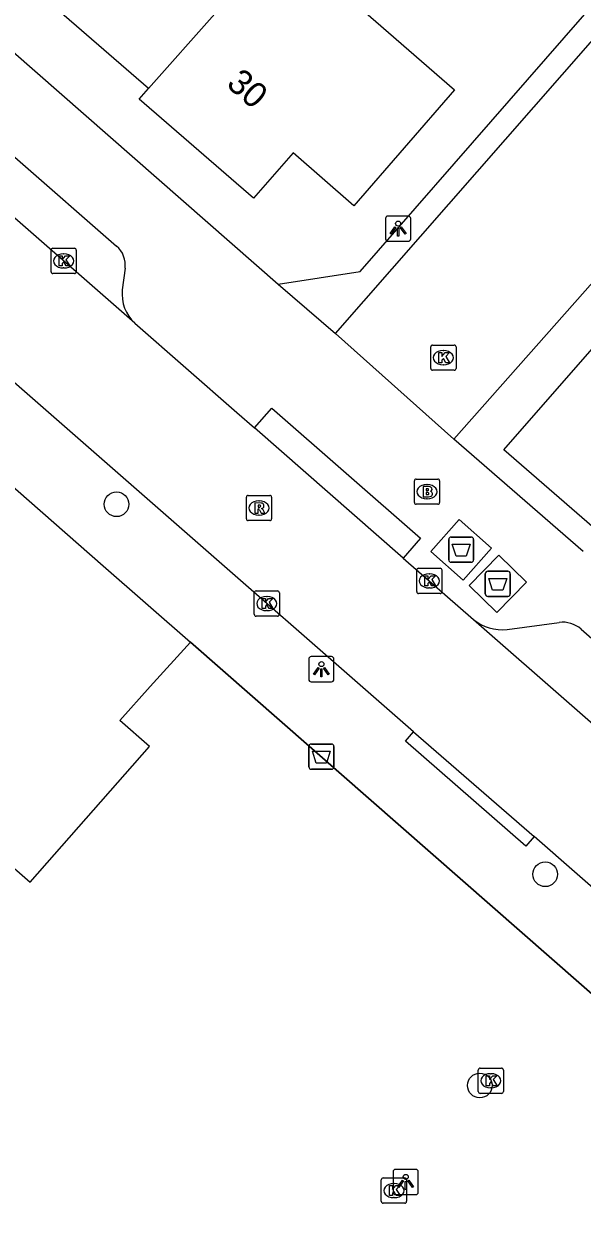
# Model space of a CAD drawing. Extents: x 158474 to 159560, y 388525 to 389605.
# Drawn here: x 158791.57 to 158813.69, y 388775.43 to 388822.77 of the extents above; entities that cross this region are included whole.
import ezdxf

# ---------------------------------------------------------------- set-up
doc = ezdxf.new("R2010")
doc.units = 0
for name, color, linetype in [('IMGEO_Afval_apart_plaats', 7, 'Continuous'), ('IMGEO_Afvalbak', 7, 'Continuous'), ('IMGEO_Boom', 7, 'Continuous'), ('IMGEO_Brandkraan', 7, 'Continuous'), ('IMGEO_Hek', 7, 'Continuous'), ('IMGEO_Kolk', 7, 'Continuous'), ('IMGEO_Lichtpunt', 7, 'Continuous'), ('IMGEO_Pand', 7, 'Continuous'), ('IMGEO_Pand_nummerreeks', 7, 'Continuous'), ('IMGEO_Rijbaan_lokaal_open', 7, 'Continuous'), ('IMGEO_Rioolput', 7, 'Continuous'), ('IMGEO_Voetpad_gesloten', 7, 'Continuous'), ('IMGEO_Voetpad_open', 7, 'Continuous')]:
    doc.layers.add(name, color=color, linetype=linetype)

msp = doc.modelspace()

# ---------------------------------------------------------------- linework, layer by layer
at = {"layer": 'IMGEO_Afval_apart_plaats'}
for p, q in [((158808.407, 388801.527), (158808.407, 388802.327)), ((158808.407, 388802.327), (158808.407, 388801.527)), ((158808.507, 388802.427), (158809.297, 388802.427)), ((158809.297, 388802.427), (158808.507, 388802.427)), ((158809.397, 388802.327), (158809.397, 388801.527)), ((158809.397, 388801.527), (158809.397, 388802.327)), ((158809.297, 388801.427), (158808.507, 388801.427)), ((158808.507, 388801.427), (158809.297, 388801.427)), ((158809.858, 388800.174), (158809.858, 388800.974)), ((158809.858, 388800.974), (158809.858, 388800.174)), ((158809.958, 388801.074), (158810.748, 388801.074)), ((158810.748, 388801.074), (158809.958, 388801.074)), ((158810.848, 388800.974), (158810.848, 388800.174)), ((158810.848, 388800.174), (158810.848, 388800.974)), ((158810.748, 388800.074), (158809.958, 388800.074)), ((158809.958, 388800.074), (158810.748, 388800.074))]:
    msp.add_line(p, q, dxfattribs=at)
for points in [[(158808.55, 388802.141), (158809.254, 388802.141), (158809.105, 388801.671), (158808.699, 388801.671), (158808.55, 388802.141)], [(158810.001, 388800.788), (158810.705, 388800.788), (158810.556, 388800.318), (158810.15, 388800.318), (158810.001, 388800.788)]]:
    msp.add_lwpolyline(points, dxfattribs=at)
for centre, start, end in [((158808.507, 388802.327), 90, 180), ((158808.507, 388802.327), 90, 180), ((158809.297, 388802.327), 0, 90), ((158809.297, 388802.327), 360, 90), ((158808.507, 388801.527), 180, 270), ((158808.507, 388801.527), 180, 270), ((158809.297, 388801.527), 270, 0), ((158809.297, 388801.527), 270, 0), ((158809.958, 388800.974), 90, 180), ((158809.958, 388800.974), 90, 180), ((158810.748, 388800.974), 0, 90), ((158810.748, 388800.974), 360, 90), ((158809.958, 388800.174), 180, 270), ((158809.958, 388800.174), 180, 270), ((158810.748, 388800.174), 270, 0), ((158810.748, 388800.174), 270, 0)]:
    msp.add_arc(centre, 0.1, start, end, dxfattribs=at)
at = {"layer": 'IMGEO_Afvalbak'}
for p, q in [((158802.968, 388794.224), (158803.758, 388794.224)), ((158803.758, 388794.224), (158802.968, 388794.224)), ((158802.868, 388793.324), (158802.868, 388794.124)), ((158802.868, 388794.124), (158802.868, 388793.324)), ((158803.858, 388794.124), (158803.858, 388793.324)), ((158803.858, 388793.324), (158803.858, 388794.124)), ((158803.758, 388793.224), (158802.968, 388793.224)), ((158802.968, 388793.224), (158803.758, 388793.224))]:
    msp.add_line(p, q, dxfattribs=at)
msp.add_lwpolyline([(158803.011, 388793.938), (158803.715, 388793.938), (158803.566, 388793.468), (158803.16, 388793.468), (158803.011, 388793.938)], dxfattribs=at)
for centre, start, end in [((158802.968, 388794.124), 90, 180), ((158802.968, 388794.124), 90, 180), ((158803.758, 388794.124), 0, 90), ((158803.758, 388794.124), 360, 90), ((158802.968, 388793.324), 180, 270), ((158802.968, 388793.324), 180, 270), ((158803.758, 388793.324), 270, 0), ((158803.758, 388793.324), 270, 0)]:
    msp.add_arc(centre, 0.1, start, end, dxfattribs=at)
at = {"layer": 'IMGEO_Boom'}
for centre in [(158795.246, 388803.729), (158812.232, 388789.064), (158809.641, 388780.692)]:
    msp.add_circle(centre, 0.489, dxfattribs=at)
at = {"layer": 'IMGEO_Brandkraan'}
for p, q in [((158807.048, 388803.801), (158807.048, 388804.653)), ((158807.123, 388804.727), (158807.975, 388804.727)), ((158808.049, 388804.653), (158808.049, 388803.801)), ((158807.536, 388804.507), (158807.561, 388804.507)), ((158807.975, 388803.727), (158807.123, 388803.727)), ((158807.559, 388803.947), (158807.534, 388803.947))]:
    msp.add_line(p, q, dxfattribs=at)
for points in [[(158807.048, 388803.801), (158807.048, 388804.653)], [(158807.123, 388804.727), (158807.975, 388804.727)], [(158808.049, 388804.653), (158808.049, 388803.801)], [(158807.396, 388804.427), (158807.396, 388804.027), (158807.609, 388804.027)], [(158807.627, 388804.427), (158807.396, 388804.427)], [(158807.575, 388804.346), (158807.521, 388804.346), (158807.521, 388804.27)], [(158807.521, 388804.27), (158807.574, 388804.27)], [(158807.583, 388804.194), (158807.521, 388804.194), (158807.521, 388804.113)], [(158807.521, 388804.113), (158807.583, 388804.113)], [(158807.975, 388803.727), (158807.123, 388803.727)]]:
    msp.add_lwpolyline(points, dxfattribs=at)
for centre, radius, start, end in [((158807.125, 388804.651), 0.0765, 91.552, 178.448), ((158807.125, 388804.651), 0.0765, 91.552, 178.448), ((158807.973, 388804.651), 0.0765, 1.552, 88.448), ((158807.973, 388804.651), 0.0765, 1.552, 88.448), ((158807.576, 388804.308), 0.0379, 267.8285, 90.9355), ((158807.584, 388804.153), 0.0404, 269.8759, 90.5077), ((158807.631, 388804.282), 0.145, 59.4692, 91.5367), ((158807.656, 388804.329), 0.0922, 285.5137, 58.1501), ((158807.661, 388804.137), 0.105, 301.3115, 78.989), ((158807.125, 388803.803), 0.0765, 181.552, 268.448), ((158807.125, 388803.803), 0.0765, 181.552, 268.448), ((158807.615, 388804.278), 0.251, 268.6676, 293.5347), ((158807.973, 388803.803), 0.0765, 271.552, 358.448), ((158807.973, 388803.803), 0.0765, 271.552, 358.448)]:
    msp.add_arc(centre, radius, start, end, dxfattribs=at)
for centre, major_axis, ratio, start_param, end_param in [((158807.535, 388804.227), (-0.387, 0.002), 0.722429, 4.712389, 7.853982), ((158807.56, 388804.227), (-0.39, 0.002), 0.717154, 1.570796, 4.712389)]:
    msp.add_ellipse(centre, major_axis=major_axis, ratio=ratio, start_param=start_param, end_param=end_param, dxfattribs=at)
at = {"layer": 'IMGEO_Hek'}
msp.add_lwpolyline([(158825.526, 388774.279), (158798.172, 388798.264)], dxfattribs=at)
at = {"layer": 'IMGEO_Kolk'}
for p, q in [((158792.65, 388812.947), (158792.65, 388813.799)), ((158792.725, 388813.873), (158793.577, 388813.873)), ((158793.138, 388813.653), (158793.163, 388813.653)), ((158793.651, 388813.799), (158793.651, 388812.947)), ((158793.161, 388813.093), (158793.136, 388813.093)), ((158793.577, 388812.873), (158792.725, 388812.873)), ((158807.697, 388809.113), (158807.697, 388809.965)), ((158807.772, 388810.039), (158808.624, 388810.039)), ((158808.185, 388809.819), (158808.21, 388809.819)), ((158808.698, 388809.965), (158808.698, 388809.113)), ((158808.624, 388809.039), (158807.772, 388809.039)), ((158808.208, 388809.259), (158808.183, 388809.259)), ((158807.141, 388800.265), (158807.141, 388801.117)), ((158807.216, 388801.191), (158808.068, 388801.191)), ((158807.629, 388800.971), (158807.654, 388800.971)), ((158808.142, 388801.117), (158808.142, 388800.265)), ((158800.774, 388800.293), (158801.626, 388800.293)), ((158807.652, 388800.411), (158807.627, 388800.411)), ((158800.699, 388799.367), (158800.699, 388800.219)), ((158801.187, 388800.073), (158801.212, 388800.073)), ((158801.7, 388800.219), (158801.7, 388799.367)), ((158808.068, 388800.191), (158807.216, 388800.191)), ((158801.21, 388799.513), (158801.185, 388799.513)), ((158801.626, 388799.293), (158800.774, 388799.293)), ((158809.652, 388781.379), (158810.504, 388781.379)), ((158809.577, 388780.453), (158809.577, 388781.305)), ((158810.065, 388781.159), (158810.09, 388781.159)), ((158810.578, 388781.305), (158810.578, 388780.453)), ((158810.088, 388780.599), (158810.063, 388780.599)), ((158810.504, 388780.379), (158809.652, 388780.379)), ((158805.737, 388776.1), (158805.737, 388776.952)), ((158805.812, 388777.026), (158806.664, 388777.026)), ((158806.225, 388776.806), (158806.25, 388776.806)), ((158806.738, 388776.952), (158806.738, 388776.1)), ((158806.248, 388776.246), (158806.223, 388776.246)), ((158806.664, 388776.026), (158805.812, 388776.026))]:
    msp.add_line(p, q, dxfattribs=at)
for points in [[(158792.65, 388812.947), (158792.65, 388813.799)], [(158792.725, 388813.873), (158793.577, 388813.873)], [(158792.971, 388813.573), (158793.094, 388813.573), (158793.094, 388813.422), (158793.224, 388813.573), (158793.388, 388813.573), (158793.242, 388813.422), (158793.395, 388813.173), (158793.243, 388813.173), (158793.158, 388813.337), (158793.094, 388813.27), (158793.094, 388813.173), (158792.971, 388813.173), (158792.971, 388813.573)], [(158793.651, 388813.799), (158793.651, 388812.947)], [(158793.577, 388812.873), (158792.725, 388812.873)], [(158807.697, 388809.113), (158807.697, 388809.965)], [(158807.772, 388810.039), (158808.624, 388810.039)], [(158808.698, 388809.965), (158808.698, 388809.113)], [(158808.018, 388809.739), (158808.141, 388809.739), (158808.141, 388809.588), (158808.271, 388809.739), (158808.435, 388809.739), (158808.289, 388809.588), (158808.442, 388809.339), (158808.29, 388809.339), (158808.205, 388809.503), (158808.141, 388809.436), (158808.141, 388809.339), (158808.018, 388809.339), (158808.018, 388809.739)], [(158808.624, 388809.039), (158807.772, 388809.039)], [(158807.141, 388800.265), (158807.141, 388801.117)], [(158807.216, 388801.191), (158808.068, 388801.191)], [(158807.462, 388800.891), (158807.585, 388800.891), (158807.585, 388800.74), (158807.715, 388800.891), (158807.879, 388800.891), (158807.733, 388800.74), (158807.886, 388800.491), (158807.734, 388800.491), (158807.649, 388800.655), (158807.585, 388800.588), (158807.585, 388800.491), (158807.462, 388800.491), (158807.462, 388800.891)], [(158808.142, 388801.117), (158808.142, 388800.265)], [(158800.774, 388800.293), (158801.626, 388800.293)], [(158800.699, 388799.367), (158800.699, 388800.219)], [(158801.02, 388799.993), (158801.143, 388799.993), (158801.143, 388799.842), (158801.273, 388799.993), (158801.437, 388799.993), (158801.291, 388799.842), (158801.444, 388799.593), (158801.292, 388799.593), (158801.207, 388799.757), (158801.143, 388799.69), (158801.143, 388799.593), (158801.02, 388799.593), (158801.02, 388799.993)], [(158801.7, 388800.219), (158801.7, 388799.367)], [(158808.068, 388800.191), (158807.216, 388800.191)], [(158801.626, 388799.293), (158800.774, 388799.293)], [(158809.652, 388781.379), (158810.504, 388781.379)], [(158809.577, 388780.453), (158809.577, 388781.305)], [(158809.898, 388781.079), (158810.021, 388781.079), (158810.021, 388780.928), (158810.151, 388781.079), (158810.315, 388781.079), (158810.169, 388780.928), (158810.322, 388780.679), (158810.17, 388780.679), (158810.085, 388780.843), (158810.021, 388780.776), (158810.021, 388780.679), (158809.898, 388780.679), (158809.898, 388781.079)], [(158810.578, 388781.305), (158810.578, 388780.453)], [(158810.504, 388780.379), (158809.652, 388780.379)], [(158805.737, 388776.1), (158805.737, 388776.952)], [(158805.812, 388777.026), (158806.664, 388777.026)], [(158806.058, 388776.726), (158806.181, 388776.726), (158806.181, 388776.575), (158806.311, 388776.726), (158806.475, 388776.726), (158806.329, 388776.575), (158806.482, 388776.326), (158806.33, 388776.326), (158806.245, 388776.49), (158806.181, 388776.423), (158806.181, 388776.326), (158806.058, 388776.326), (158806.058, 388776.726)], [(158806.738, 388776.952), (158806.738, 388776.1)], [(158806.664, 388776.026), (158805.812, 388776.026)]]:
    msp.add_lwpolyline(points, dxfattribs=at)
for centre, start, end in [((158792.727, 388813.797), 91.552, 178.448), ((158792.727, 388813.797), 91.552, 178.448), ((158793.575, 388813.797), 1.552, 88.448), ((158793.575, 388813.797), 1.552, 88.448), ((158792.727, 388812.949), 181.552, 268.448), ((158792.727, 388812.949), 181.552, 268.448), ((158793.575, 388812.949), 271.552, 358.448), ((158793.575, 388812.949), 271.552, 358.448), ((158807.774, 388809.963), 91.552, 178.448), ((158807.774, 388809.963), 91.552, 178.448), ((158808.622, 388809.963), 1.552, 88.448), ((158808.622, 388809.963), 1.552, 88.448), ((158807.774, 388809.115), 181.552, 268.448), ((158807.774, 388809.115), 181.552, 268.448), ((158808.622, 388809.115), 271.552, 358.448), ((158808.622, 388809.115), 271.552, 358.448), ((158807.218, 388801.115), 91.552, 178.448), ((158807.218, 388801.115), 91.552, 178.448), ((158808.066, 388801.115), 1.552, 88.448), ((158808.066, 388801.115), 1.552, 88.448), ((158800.776, 388800.217), 91.552, 178.448), ((158800.776, 388800.217), 91.552, 178.448), ((158801.624, 388800.217), 1.552, 88.448), ((158801.624, 388800.217), 1.552, 88.448), ((158807.218, 388800.267), 181.552, 268.448), ((158807.218, 388800.267), 181.552, 268.448), ((158808.066, 388800.267), 271.552, 358.448), ((158808.066, 388800.267), 271.552, 358.448), ((158800.776, 388799.369), 181.552, 268.448), ((158800.776, 388799.369), 181.552, 268.448), ((158801.624, 388799.369), 271.552, 358.448), ((158801.624, 388799.369), 271.552, 358.448), ((158809.654, 388781.303), 91.552, 178.448), ((158809.654, 388781.303), 91.552, 178.448), ((158810.502, 388781.303), 1.552, 88.448), ((158810.502, 388781.303), 1.552, 88.448), ((158809.654, 388780.455), 181.552, 268.448), ((158809.654, 388780.455), 181.552, 268.448), ((158810.502, 388780.455), 271.552, 358.448), ((158810.502, 388780.455), 271.552, 358.448), ((158805.814, 388776.95), 91.552, 178.448), ((158805.814, 388776.95), 91.552, 178.448), ((158806.662, 388776.95), 1.552, 88.448), ((158806.662, 388776.95), 1.552, 88.448), ((158805.814, 388776.102), 181.552, 268.448), ((158805.814, 388776.102), 181.552, 268.448), ((158806.662, 388776.102), 271.552, 358.448), ((158806.662, 388776.102), 271.552, 358.448)]:
    msp.add_arc(centre, 0.0765, start, end, dxfattribs=at)
for centre, major_axis, ratio, start_param, end_param in [((158793.137, 388813.373), (-0.387, 0.002), 0.722429, 4.712389, 7.853982), ((158793.162, 388813.373), (-0.39, 0.002), 0.717154, 1.570796, 4.712389), ((158808.184, 388809.539), (-0.387, 0.002), 0.722429, 4.712389, 7.853982), ((158808.209, 388809.539), (-0.39, 0.002), 0.717154, 1.570796, 4.712389), ((158807.628, 388800.691), (-0.387, 0.002), 0.722429, 4.712389, 7.853982), ((158807.653, 388800.691), (-0.39, 0.002), 0.717154, 1.570796, 4.712389), ((158801.186, 388799.793), (-0.387, 0.002), 0.722429, 4.712389, 7.853982), ((158801.211, 388799.793), (-0.39, 0.002), 0.717154, 1.570796, 4.712389), ((158810.064, 388780.879), (-0.387, 0.002), 0.722429, 4.712389, 7.853982), ((158810.089, 388780.879), (-0.39, 0.002), 0.717154, 1.570796, 4.712389), ((158806.224, 388776.526), (-0.387, 0.002), 0.722429, 4.712389, 7.853982), ((158806.249, 388776.526), (-0.39, 0.002), 0.717154, 1.570796, 4.712389)]:
    msp.add_ellipse(centre, major_axis=major_axis, ratio=ratio, start_param=start_param, end_param=end_param, dxfattribs=at)
at = {"layer": 'IMGEO_Lichtpunt'}
for p, q in [((158805.905, 388815.056), (158805.905, 388814.249)), ((158805.905, 388815.056), (158805.905, 388814.249)), ((158806.807, 388815.151), (158805.999, 388815.151)), ((158806.807, 388815.151), (158805.999, 388815.151)), ((158806.901, 388814.249), (158806.901, 388815.056)), ((158806.901, 388814.249), (158806.901, 388815.056)), ((158805.999, 388814.155), (158806.807, 388814.155)), ((158805.999, 388814.155), (158806.807, 388814.155)), ((158802.863, 388797.594), (158802.863, 388796.787)), ((158802.863, 388797.594), (158802.863, 388796.787)), ((158803.765, 388797.689), (158802.957, 388797.689)), ((158803.765, 388797.689), (158802.957, 388797.689)), ((158803.859, 388796.787), (158803.859, 388797.594)), ((158803.859, 388796.787), (158803.859, 388797.594)), ((158802.957, 388796.693), (158803.765, 388796.693)), ((158802.957, 388796.693), (158803.765, 388796.693)), ((158806.207, 388777.271), (158806.207, 388776.464)), ((158806.207, 388777.271), (158806.207, 388776.464)), ((158807.109, 388777.366), (158806.301, 388777.366)), ((158807.109, 388777.366), (158806.301, 388777.366)), ((158807.203, 388776.464), (158807.203, 388777.271)), ((158807.203, 388776.464), (158807.203, 388777.271)), ((158806.301, 388776.37), (158807.109, 388776.37)), ((158806.301, 388776.37), (158807.109, 388776.37))]:
    msp.add_line(p, q, dxfattribs=at)
for points in [[(158806.279, 388814.72), (158806.318, 388814.692), (158806.13, 388814.43), (158806.092, 388814.457), (158806.279, 388814.72)], [(158806.381, 388814.672), (158806.428, 388814.672), (158806.428, 388814.35), (158806.381, 388814.35), (158806.381, 388814.672)], [(158806.491, 388814.692), (158806.529, 388814.719), (158806.716, 388814.457), (158806.677, 388814.429), (158806.491, 388814.692)], [(158803.237, 388797.258), (158803.276, 388797.23), (158803.088, 388796.968), (158803.05, 388796.995), (158803.237, 388797.258)], [(158803.339, 388797.21), (158803.386, 388797.21), (158803.386, 388796.888), (158803.339, 388796.888), (158803.339, 388797.21)], [(158803.449, 388797.23), (158803.487, 388797.257), (158803.674, 388796.995), (158803.635, 388796.967), (158803.449, 388797.23)], [(158806.581, 388776.935), (158806.62, 388776.907), (158806.432, 388776.645), (158806.394, 388776.672), (158806.581, 388776.935)], [(158806.683, 388776.887), (158806.73, 388776.887), (158806.73, 388776.565), (158806.683, 388776.565), (158806.683, 388776.887)], [(158806.793, 388776.907), (158806.831, 388776.934), (158807.018, 388776.672), (158806.979, 388776.644), (158806.793, 388776.907)]]:
    msp.add_lwpolyline(points, dxfattribs=at)
for centre in [(158806.404, 388814.854), (158803.362, 388797.392), (158806.706, 388777.069)]:
    msp.add_circle(centre, 0.0994, dxfattribs=at)
for centre, start, end in [((158805.999, 388815.056), 90, 180), ((158805.999, 388815.056), 90, 180), ((158806.807, 388815.056), 0, 90), ((158806.807, 388815.056), 0, 90), ((158805.999, 388814.249), 180, 270), ((158805.999, 388814.249), 180, 270), ((158806.807, 388814.249), 270, 0), ((158806.807, 388814.249), 270, 360), ((158802.957, 388797.594), 90, 180), ((158802.957, 388797.594), 90, 180), ((158803.765, 388797.594), 0, 90), ((158803.765, 388797.594), 0, 90), ((158802.957, 388796.787), 180, 270), ((158802.957, 388796.787), 180, 270), ((158803.765, 388796.787), 270, 0), ((158803.765, 388796.787), 270, 360), ((158806.301, 388777.271), 90, 180), ((158806.301, 388777.271), 90, 180), ((158807.109, 388777.271), 0, 90), ((158807.109, 388777.271), 0, 90), ((158806.301, 388776.464), 180, 270), ((158806.301, 388776.464), 180, 270), ((158807.109, 388776.464), 270, 0), ((158807.109, 388776.464), 270, 360)]:
    msp.add_arc(centre, 0.0946, start, end, dxfattribs=at)
at = {"layer": 'IMGEO_Pand'}
for points in [[(158801.77, 388826.139), (158801.958, 388825.976), (158802.404, 388825.587), (158808.64, 388820.153), (158804.648, 388815.563), (158802.238, 388817.653), (158800.671, 388815.857), (158796.137, 388819.787), (158796.506, 388820.209)], [(158801.77, 388826.139), (158796.506, 388820.209)], [(158796.506, 388820.209), (158792.287, 388823.886)], [(158788.4, 388806.822), (158794.714, 388801.292), (158798.172, 388798.264)], [(158805.723, 388741.649), (158796.329, 388750), (158794.531, 388751.598), (158793.515, 388750.405), (158782.155, 388760.402), (158781.158, 388759.289), (158770.201, 388768.931), (158771.896, 388770.851), (158774.295, 388768.733), (158776.797, 388771.566), (158775.714, 388772.533), (158780.862, 388778.415), (158781.952, 388777.459), (158786.674, 388782.839), (158785.492, 388783.869), (158790.672, 388789.76), (158791.819, 388788.744), (158796.547, 388794.127), (158795.371, 388795.164), (158796.583, 388796.505), (158798.172, 388798.264)]]:
    msp.add_lwpolyline(points, dxfattribs=at)
at = {"layer": 'IMGEO_Rijbaan_lokaal_open'}
for points in [[(158795.971, 388810.903), (158760.339, 388842.098)], [(158803.922, 388810.501), (158817.392, 388825.895), (158820.104, 388828.995)], [(158824.946, 388824.766), (158822.181, 388821.641), (158808.612, 388806.31)], [(158807.018, 388794.713), (158796.782, 388803.661), (158782.389, 388816.244)], [(158795.971, 388810.903), (158800.014, 388807.365), (158800.712, 388806.754)], [(158808.612, 388806.31), (158803.922, 388810.501)], [(158806.606, 388801.596), (158800.712, 388806.754)], [(158806.606, 388801.596), (158809.387, 388799.161)], [(158809.387, 388799.161), (158825.712, 388784.875), (158827.828, 388783.04)], [(158807.018, 388794.713), (158811.795, 388790.555)], [(158826.434, 388774.844), (158827.866, 388776.475), (158811.795, 388790.555)]]:
    msp.add_lwpolyline(points, dxfattribs=at)
at = {"layer": 'IMGEO_Rioolput'}
for p, q in [((158800.466, 388804.08), (158801.318, 388804.08)), ((158800.391, 388803.154), (158800.391, 388804.006)), ((158800.879, 388803.86), (158800.904, 388803.86)), ((158801.392, 388804.006), (158801.392, 388803.154)), ((158800.902, 388803.3), (158800.877, 388803.3)), ((158801.318, 388803.08), (158800.466, 388803.08))]:
    msp.add_line(p, q, dxfattribs=at)
for points in [[(158800.466, 388804.08), (158801.318, 388804.08)], [(158800.391, 388803.154), (158800.391, 388804.006)], [(158800.98, 388803.778), (158800.728, 388803.78), (158800.728, 388803.38)], [(158800.906, 388803.699), (158800.852, 388803.699), (158800.852, 388803.618)], [(158800.852, 388803.618), (158800.904, 388803.618)], [(158801.392, 388804.006), (158801.392, 388803.154)], [(158800.728, 388803.38), (158800.852, 388803.38), (158800.852, 388803.542), (158800.863, 388803.542)], [(158800.91, 388803.513), (158800.981, 388803.38), (158801.121, 388803.38), (158801.056, 388803.506)], [(158801.318, 388803.08), (158800.466, 388803.08)]]:
    msp.add_lwpolyline(points, dxfattribs=at)
for centre, radius, start, end in [((158800.468, 388804.004), 0.0765, 91.552, 178.448), ((158800.468, 388804.004), 0.0765, 91.552, 178.448), ((158801.316, 388804.004), 0.0765, 1.552, 88.448), ((158801.316, 388804.004), 0.0765, 1.552, 88.448), ((158800.888, 388803.807), 0.19, 274.7715, 282.9687), ((158800.912, 388803.603), 0.0964, 77.0061, 93.1865), ((158800.926, 388803.66), 0.0378, 276.6634, 79.6772), ((158800.979, 388803.668), 0.109, 350.3612, 89.416), ((158800.977, 388803.668), 0.112, 277.5842, 350.9817), ((158800.468, 388803.156), 0.0765, 181.552, 268.448), ((158800.468, 388803.156), 0.0765, 181.552, 268.448), ((158800.862, 388803.489), 0.0533, 26.0293, 88.6989), ((158800.961, 388803.453), 0.108, 29.5134, 73.7905), ((158801.316, 388803.156), 0.0765, 271.552, 358.448), ((158801.316, 388803.156), 0.0765, 271.552, 358.448)]:
    msp.add_arc(centre, radius, start, end, dxfattribs=at)
for centre, major_axis, ratio, start_param, end_param in [((158800.878, 388803.58), (-0.387, 0.002), 0.722429, 4.712389, 7.853982), ((158800.903, 388803.58), (-0.39, 0.002), 0.717154, 1.570796, 4.712389)]:
    msp.add_ellipse(centre, major_axis=major_axis, ratio=ratio, start_param=start_param, end_param=end_param, dxfattribs=at)
at = {"layer": 'IMGEO_Voetpad_gesloten'}
for points in [[(158808.825, 388803.13), (158810.105, 388801.993), (158808.978, 388800.724), (158807.698, 388801.861), (158808.825, 388803.13)], [(158810.391, 388801.712), (158811.49, 388800.641), (158810.314, 388799.435), (158809.215, 388800.506), (158810.391, 388801.712)]]:
    msp.add_lwpolyline(points, dxfattribs=at)
at = {"layer": 'IMGEO_Voetpad_open'}
for points in [[(158801.652, 388812.449), (158804.894, 388812.957), (158816.712, 388826.499), (158846.015, 388860.076)], [(158763.278, 388846.106), (158801.652, 388812.449)], [(158763.843, 388841.448), (158795.249, 388813.963)], [(158814.381, 388802.592), (158810.595, 388805.883), (158820.088, 388816.74)], [(158795.582, 388813.083), (158795.471, 388812.224)], [(158801.652, 388812.449), (158803.922, 388810.501)], [(158800.712, 388806.754), (158801.397, 388807.537), (158807.291, 388802.379), (158806.606, 388801.596)], [(158813.735, 388801.853), (158808.612, 388806.31)], [(158810.726, 388798.764), (158812.782, 388799.043)], [(158813.654, 388798.781), (158826.902, 388787.187)], [(158798.172, 388798.264), (158825.526, 388774.279), (158825.755, 388774.071)], [(158811.795, 388790.555), (158811.467, 388790.178), (158806.69, 388794.336), (158807.018, 388794.713)]]:
    msp.add_lwpolyline(points, dxfattribs=at)
for centre, radius, start, end in [((158794.595, 388813.213), 0.995, 352.517, 48.9372), ((158797.043, 388812.064), 1.58, 174.1837, 227.2797), ((158810.526, 388800.548), 1.795, 230.5878, 276.3831), ((158812.931, 388797.957), 1.096, 48.7301, 97.8232)]:
    msp.add_arc(centre, radius, start, end, dxfattribs=at)

# ---------------------------------------------------------------- texts
at = {"layer": 'IMGEO_Pand_nummerreeks'}
msp.add_text('30', height=1, rotation=318.9247, dxfattribs=at).set_placement((158799.555, 388820.323))

doc.saveas('drawing.dxf')
